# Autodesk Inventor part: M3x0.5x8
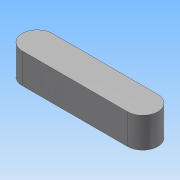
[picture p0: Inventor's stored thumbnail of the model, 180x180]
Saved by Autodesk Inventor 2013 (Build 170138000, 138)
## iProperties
Company: 한국ATC센터
Created: 2009-02
Part Number: M3x0.5x8
Document SubType Name: Modeling
Designer: KYOUNG IL JANG
Density: 7.86 g/cm^3
Mass: 2.15573 g
Surface Area: 2.99398 cm^2
Volume: 0.274265 cm^3
Vendor: CBT Solutions
Material: 강철, 연강
Author: KYOUNG IL JANG
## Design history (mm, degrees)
sketch "스케치1"
  geometry: L1 (0, 2)-(14, 2); L2 (0, -2)-(14, -2); A1 r 2 centre (0, 0) between (0, 2) and (0, -2); A2 r 2 centre (14, 0) between (14, -2) and (14, 2); 1 further point
  constraints: 4 end point, 4 point on circle, 3 tangent, 2 centre point, 1 coincident, 1 equal radius, 1 horizontal alignment, 1 parallel
  dimensions: "d0" = 4 distance between parallel lines of L2 L1; "d1" = 18 dimension on A2 A1
extrude "돌출1" new body sketch "스케치1" distance "d2" = 4; taper "d3" = 0 deg
node "솔리드1"
